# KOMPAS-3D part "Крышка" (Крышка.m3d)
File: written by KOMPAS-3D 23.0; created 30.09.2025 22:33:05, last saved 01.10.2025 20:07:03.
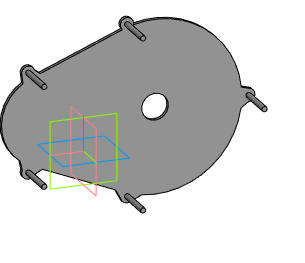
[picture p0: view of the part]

Document properties: Автор: Inspektor_Kot; Полное имя файла: C:\Users\Lost\Desktop\Варианты\Вариант 7\Вариант 7\Крышка.m3d

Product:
- Part/product: Крышка
    Масса: 0.423039

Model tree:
1. Эскиз:2  (with: Элемент выдавливания:4, Элемент выдавливания:5)
2. Элемент выдавливания:1
     Расстояние 1 = 3
3. Эскиз:3  (with: Элемент выдавливания:1)
4. Элемент выдавливания:2
     Расстояние 1 = -35
5. Эскиз:4  (with: Элемент выдавливания:1, Элемент выдавливания:2)  (labels: Цилиндрическое зубчатое зацепление1\Шестерёнка большая)
6. Элемент выдавливания:4
     Расстояние 2 = 10

Referenced files in C:\Users\Lost\Desktop\Варианты\Вариант 7\Вариант 7\: Мотор-редуктор.a3d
